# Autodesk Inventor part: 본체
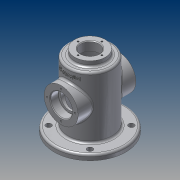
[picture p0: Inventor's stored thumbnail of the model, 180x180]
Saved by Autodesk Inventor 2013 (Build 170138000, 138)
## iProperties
Created: 2014-12
Part Number: 본체
Material: 알루미늄 6061
Document SubType Name: Modeling
Designer: CAD-B18
Density: 2.71 g/cm^3
Mass: 479.555 g
Surface Area: 607.361 cm^2
Volume: 176.958 cm^3
Author: CAD-B18
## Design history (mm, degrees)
sketch "스케치1"
  geometry: C1 r 32.5 at (0, 0); 1 further point
  constraints: 1 centre point
  dimensions: "d1" = 65 diameter of C1
extrude "돌출1" new body sketch "스케치1" distance "d2" = 98; taper "d3" = 0 deg
fillet "모깎기1" dims "d4" = 3
feature "쉘1" dims "d5" = 5
fillet "모깎기2" dims "d6" = 3
sketch "스케치2"
  geometry: C1 r 52.5 at (0, 0); C2 r 27.5 at (0, 0) reference; 1 further point
  constraints: 1 centre point, 1 coincident
  dimensions: "d7" = 105 diameter of C1
extrude "돌출2" join sketch "스케치2" distance "d8" = 8; taper "d9" = 0 deg
fillet "모깎기3" dims "d10" = 3
node "작업 평면2"
sketch "스케치3"
  geometry: L1 (27.5, 0)-(-27.5, 0) reference; C1 r 25 at (0, 55); 1 further point
  constraints: 1 centre point, 1 vertical alignment
  dimensions: "d12" = 50 diameter of C1; "d13" = 55 distance from line of L1 C1.centre
extrude "돌출3" join sketch "스케치3" stored distance "d14" = 8; taper "d15" = 0 deg
hole "구멍1" diameter "d18" = 25; stored, may be unused: countersink angle "d22" = 90 deg, drill point angle "d24" = 118 deg; dims "d16" = 10, "d17" = 10, "d19" = 6, "d20" = 32, "d21" = 12, "d23" = 8
sketch "스케치4"
  geometry: C1 r 22.5 at (0, 0); 1 further point
  constraints: 1 centre point, 1 coincident
  dimensions: "d25" = 45 diameter of C1
extrude "돌출4" join sketch "스케치4" distance "d26" = 8; taper "d27" = 0 deg
fillet "모깎기4" dims "d28" = 3
hole "구멍2" diameter "d31" = 27; stored, may be unused: countersink angle "d35" = 90 deg, drill point angle "d37" = 118 deg; dims "d29" = 10, "d30" = 10, "d32" = 6, "d33" = 32, "d34" = 12, "d36" = 8
chamfer "모따기1" distance "d38" = 1; stored, may be unused: second distance "d39" = 2, angle "d40" = 45 deg
fillet "모깎기5" dims "d41" = 0.3
sketch "스케치5"
  geometry: L1 (52.5, -55)-(-52.5, -55) reference; 2 further points
  constraints: 1 vertical alignment
  dimensions: "d42" = 75.5 distance from line of L1 point (0, 20.5)
hole "구멍3" sketch "스케치5" at (0, 20.5) diameter "d43" = 2.459; stored, may be unused: countersink angle "d47" = 90 deg, drill point angle "d49" = 118 deg; dims "d44" = 6, "d45" = 32, "d46" = 12, "d48" = 8
sketch "스케치6"
  geometry: 2 further points
  constraints: 1 vertical alignment
  dimensions: "d53" = 17.5 distance of point (0, 0) point (0, 17.5)
hole "구멍4" sketch "스케치6" at (0, 17.5) diameter "d54" = 2.459; stored, may be unused: countersink angle "d58" = 90 deg, drill point angle "d60" = 118 deg; dims "d55" = 6, "d56" = 32, "d57" = 12, "d59" = 8
node "작업 평면3"
sketch "스케치7"
  geometry: L1 (-29.5, 98)-(29.5, 98) reference; 2 further points
  constraints: 1 vertical alignment, 1 other
  dimensions: "d64" = 9 distance from line of L1 point (0, 89)
feature "엠보싱1" sketch "스케치7" dims "d65" = 1, "d66" = 0
sketch "스케치8" dims "d67" = 86
  geometry: L1 (0, 0)-(68.728, -68.728); L2 (0, 0)-(97.196, 0); 2 further points
  constraints: 4 end point, 1 coincident, 1 equal length, 1 horizontal, 1 point on line, 3 other
  dimensions: "d68" = 45 deg angle of L1 L2
hole "구멍5" sketch "스케치8" at (30.406, -30.406) diameter "d69" = 8; stored, may be unused: countersink angle "d73" = 90 deg, drill point angle "d75" = 118 deg; dims "d70" = 6, "d71" = 32, "d72" = 12, "d74" = 8
node "솔리드1"
mirror "대칭1"
mirror "대칭2"
pattern_circular "원형 패턴1" dims angle "d51" = 360 deg
mirror "대칭3"
pattern_circular "원형 패턴2" dims angle "d62" = 360 deg
pattern_circular "원형 패턴3" dims angle "d77" = 360 deg
other parameters: "d11" = -42.5
